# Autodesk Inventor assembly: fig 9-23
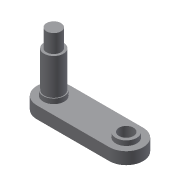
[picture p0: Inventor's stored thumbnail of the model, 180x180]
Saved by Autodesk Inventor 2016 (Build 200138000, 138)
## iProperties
Shininess: 64.0
Length Units: 11269
Angle Units: 11279
Time Units: 11290
Mass Units: 11283
Length Display Precision: 3
Angle Display Precision: 2
Created: 2002-01
Part Number: fig 9-23
Document SubType Name: Assembly
Designer: ***
Density: 0.0
Volumn: 0.0
Area: 0.0
PropertySet Name: Model Information
Control State: 0
Master: False
Checked Out: False
Author: ***
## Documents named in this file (3)
- D:\KAVITA\Autodesk Inventor_ 2016 Project_Kavita\Inventor_Part Files\Inventor_2016_Part\c09_Inv_2016\c09_inv_2016_prt\fig 9-23.iam
- D:\KAVITA\Autodesk Inventor_ 2016 Project_Kavita\Inventor_Part Files\Inventor_2016_Part\c09_Inv_2016\c09_inv_2016_prt\Part5.ipt
- D:\KAVITA\Autodesk Inventor_ 2016 Project_Kavita\Inventor_Part Files\Inventor_2016_Part\c09_Inv_2016\c09_inv_2016_prt\Part6.ipt
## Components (2 placed, 2 different names)
1. Part5:1 — Insert:1
2. Part6:1 — Insert:1
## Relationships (1: Insert 1)
- Insert:1: Part5:1 ↔ Part6:1
